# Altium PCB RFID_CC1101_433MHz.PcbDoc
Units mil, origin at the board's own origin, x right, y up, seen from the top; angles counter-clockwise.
Board outline 1500 x 2000 mil, 4 copper layers (Top Layer, GND Plane, POWER Plane, Bottom Layer), stack 16.312 mil thick; 74 components, 57 nets, 265 pads, 134 vias.
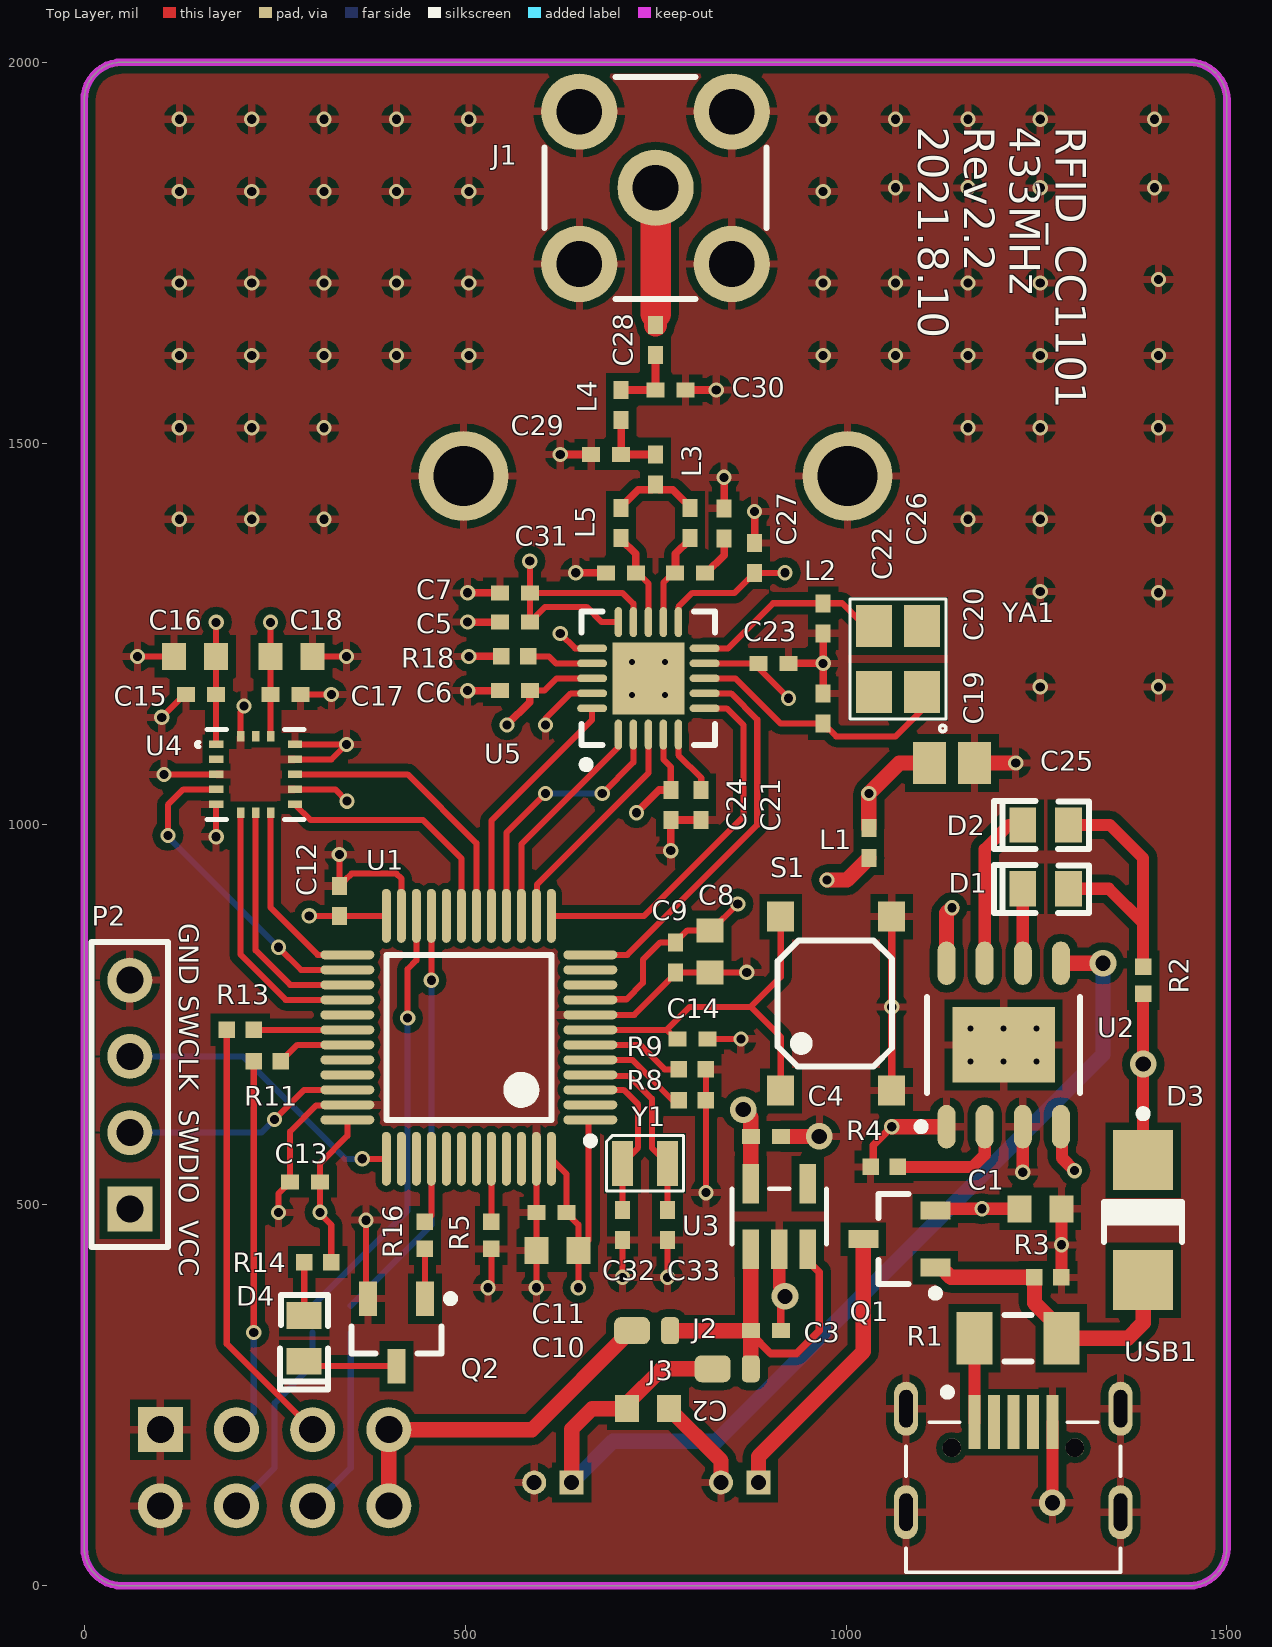
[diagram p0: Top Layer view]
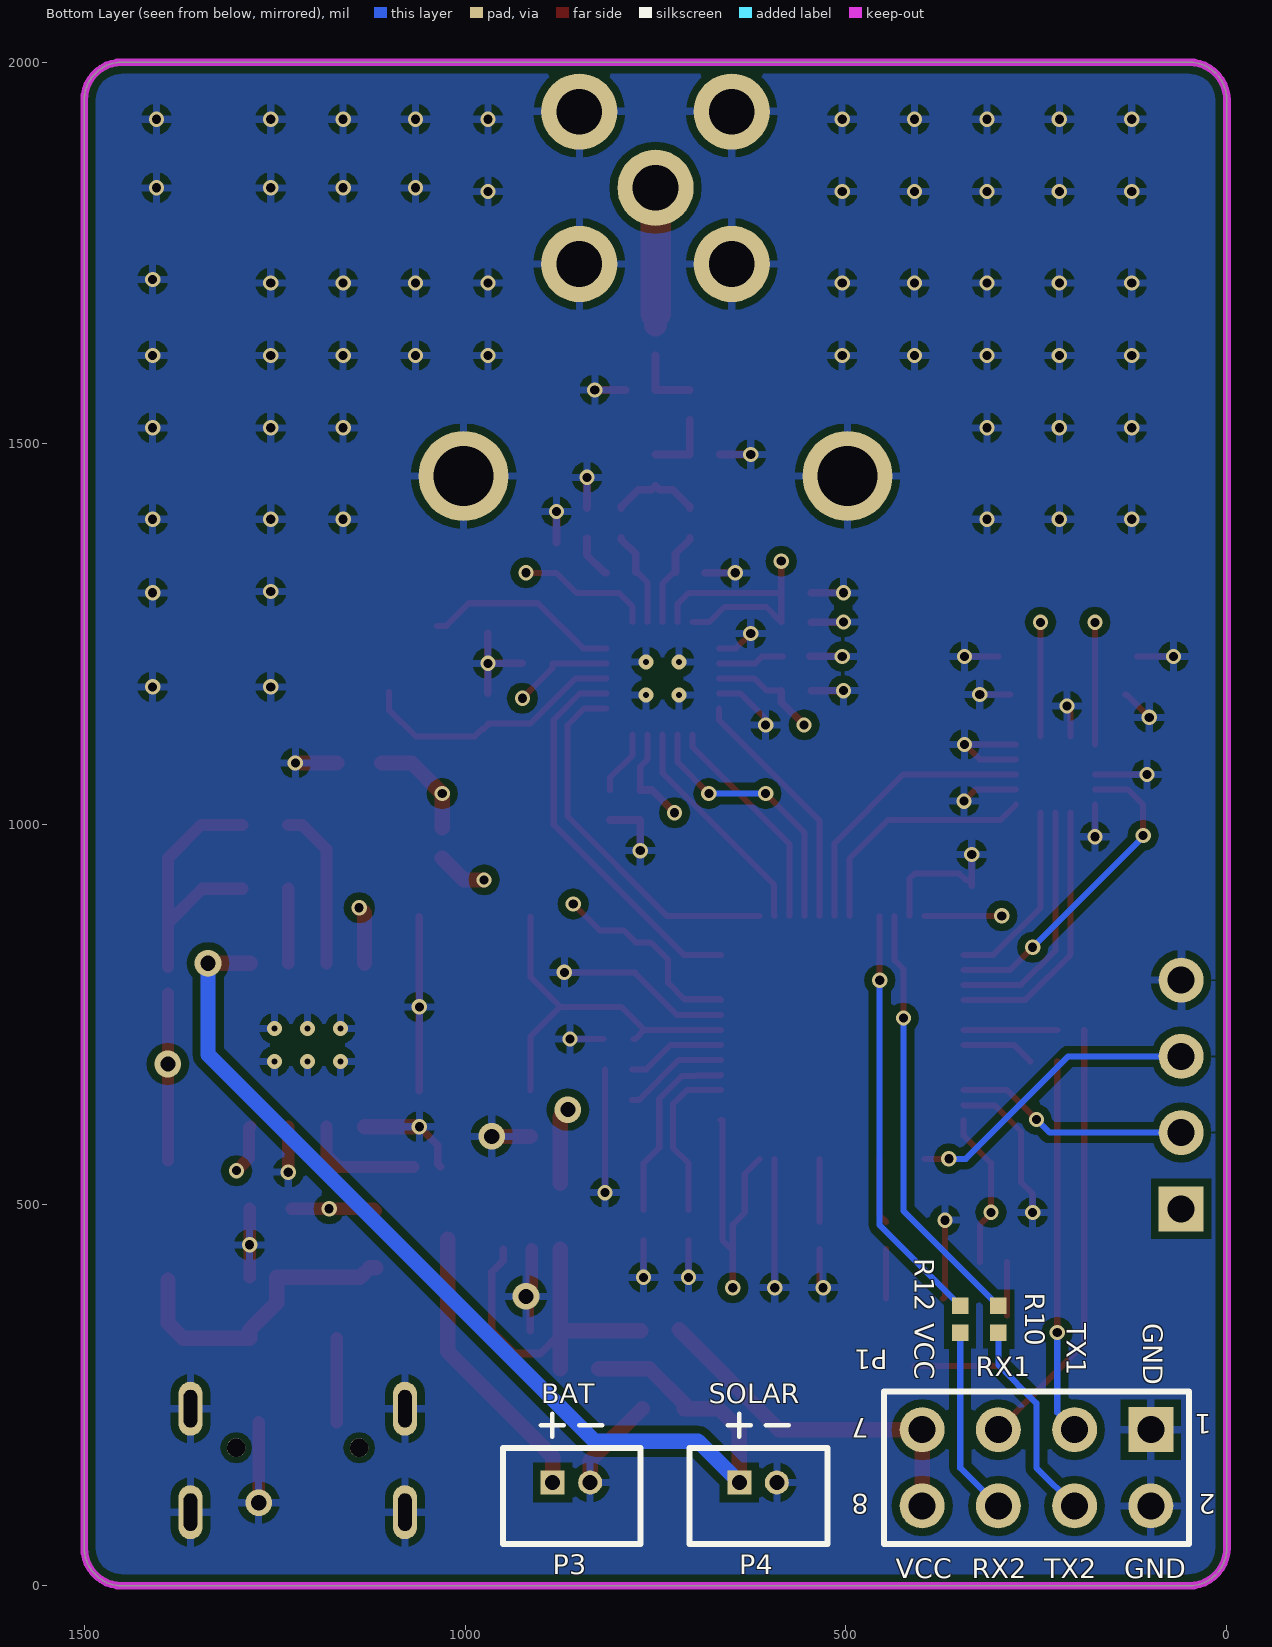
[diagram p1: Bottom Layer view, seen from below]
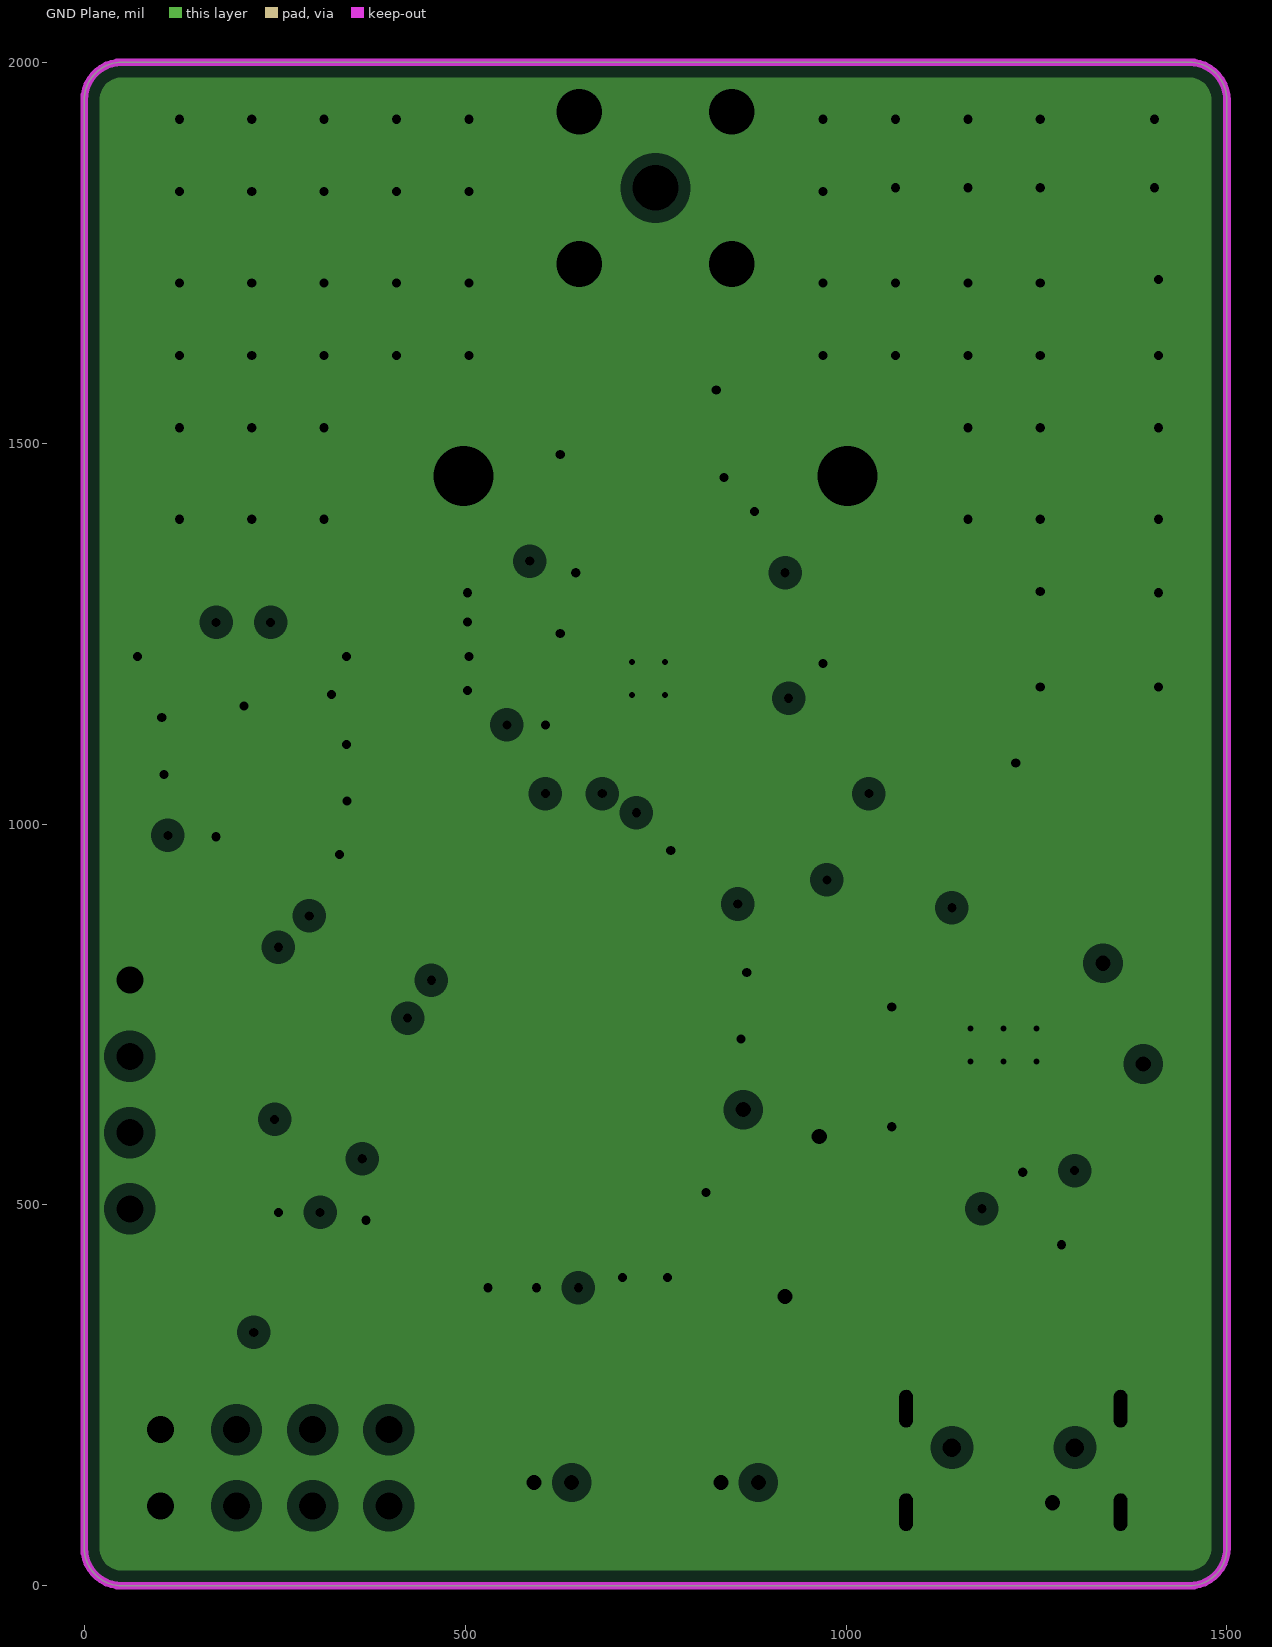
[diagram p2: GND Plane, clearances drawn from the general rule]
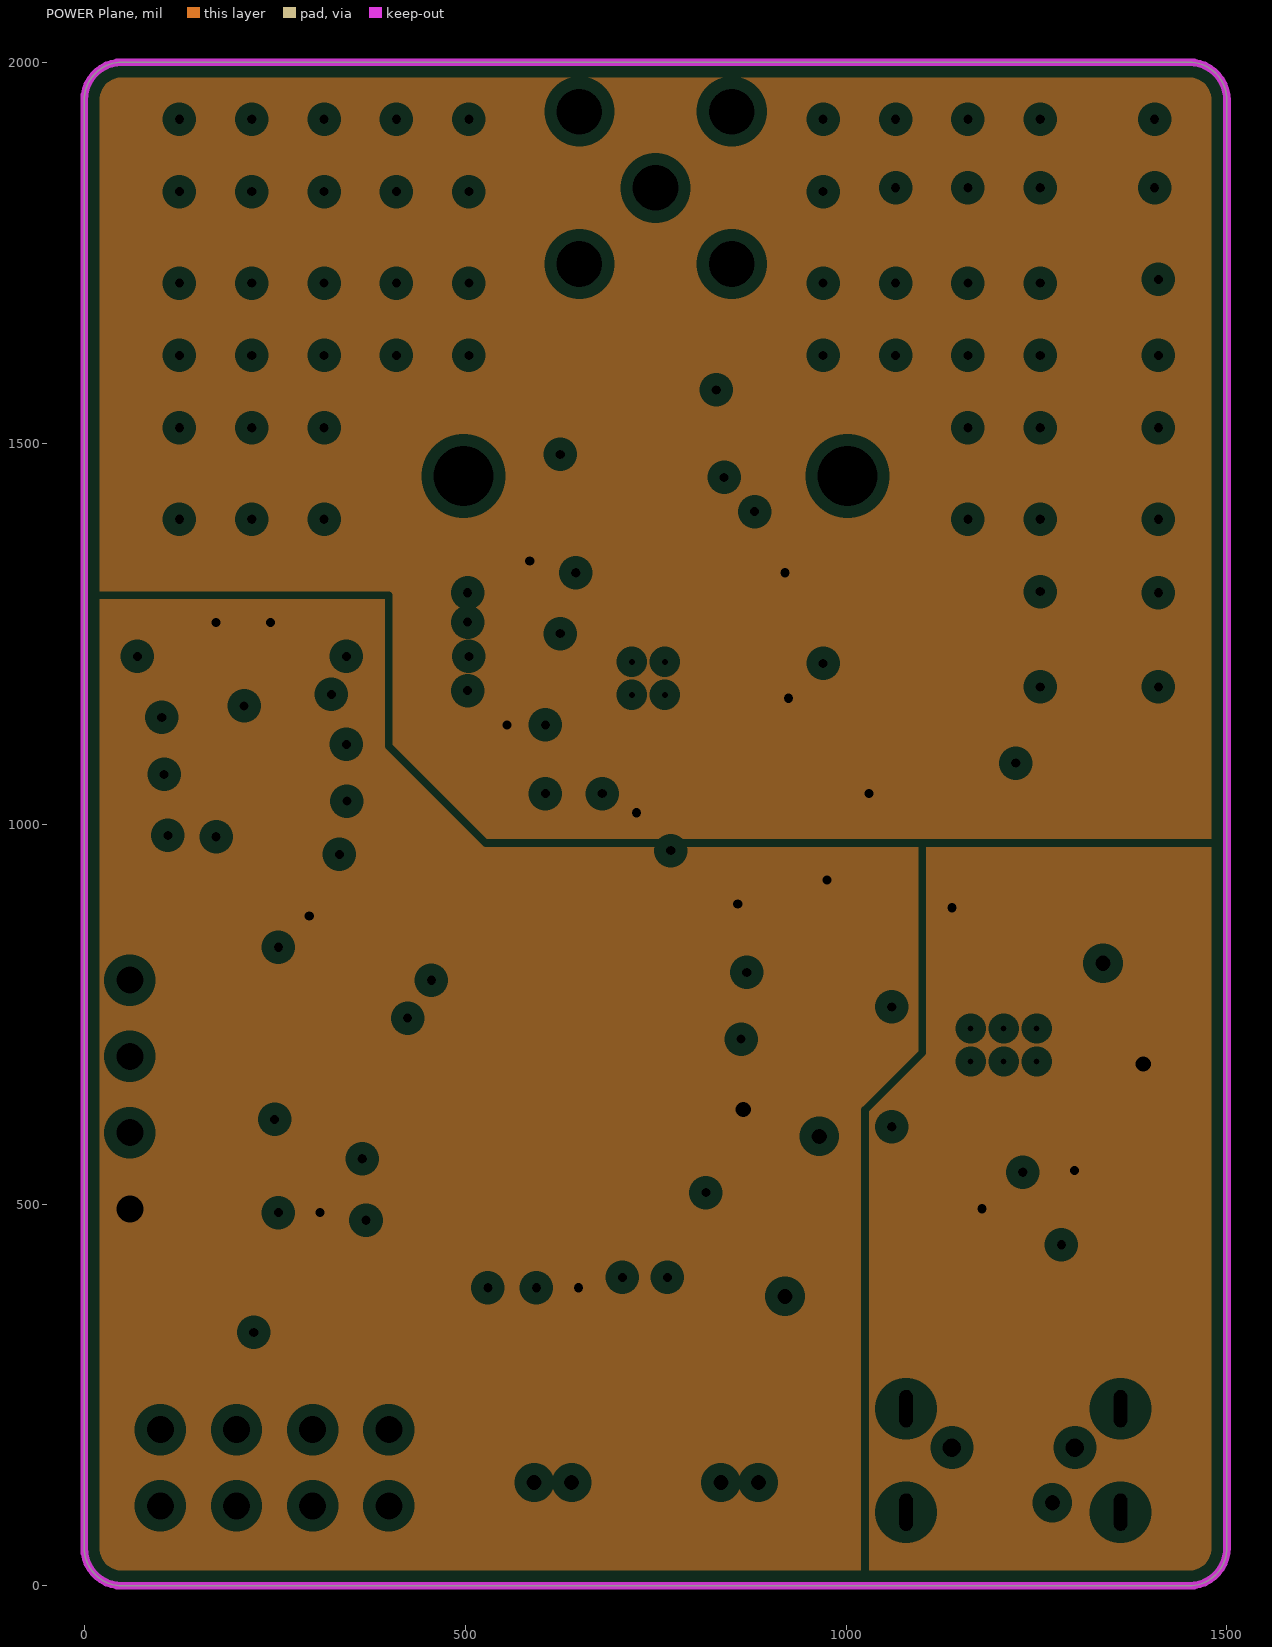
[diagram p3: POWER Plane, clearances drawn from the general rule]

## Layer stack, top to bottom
Top Solder: solder mask 0.4, Solder Resist, Dk 3.5
Top Layer: signal copper 1.3779
Dielectric 1: core 4, Core-009, Dk 4.5
GND Plane: plane copper 1.3779, net GND
Dielectric 3: prepreg 2.8, PP-006, Dk 4.1
POWER Plane: plane copper 1.3779, net (Multiple Nets)
Dielectric 2: core 4, Core-009, Dk 4.5
Bottom Layer: signal copper 1.3779
Bottom Solder: solder mask 0.4, Solder Resist, Dk 3.5

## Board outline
0,50 ccw(c50,50) 50,0 1450,0 ccw(c1450,50) 1500,50 1500,1950 ccw(c1450,1950) 1450,2000 50,2000 ccw(c50,1950) 0,1950

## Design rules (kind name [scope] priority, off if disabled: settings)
Clearance Clearance_8mil [(IsPad and InComponent('U1')) or (IsPad and InComponent('U4')) or (IsPad and InComponent('U5')) or (IsPad and InComponent('USB1'))] p1: gap=8 ignorepadtopadclearanceinfootprint=TRUE
Clearance [All] p2: gap=10 ignorepadtopadclearanceinfootprint=FALSE except(0: Arc-Hole Track-Hole SMDPad-Hole THPad-Hole Via-Hole Fill-Hole Poly-Hole Region-Hole Text-Hole)
MinimumSolderMaskSliver [All] p1: minsoldermaskwidth=1.4
PlaneClearance [All] p1: clearance=16
PlaneConnect [All] p1: pad.planeconnectstyle=Relief pad.reliefexpansion=20 pad.reliefentries=4 pad.reliefconductorwidth=10 pad.reliefairgap=10 via.planeconnectstyle=Relief via.reliefexpansion=16 via.reliefentries=4 via.reliefconductorwidth=10 via.reliefairgap=10
PolygonConnect [All] p1: connectstyle=Relief reliefconductorwidth=10 reliefentries=4 polygonreliefangle="90 Angle" airgapwidth=10
RoutingVias [All] p1: holewidth=12 width=20 viastyle="Through Hole" minholewidth=6 minwidth=16 maxholewidth=28 maxwidth=50
SilkToSilkClearance [All] p1: silktosilkclearance=6
SilkToSolderMaskClearance [IsPad] p1: minsilkscreentomaskgap=0 clearancetoexposedcopper=TRUE
SolderMaskExpansion [All] p1: expansion=4
Width Width_PW [InNet('BAT+') or InNet('SOLAR+') or InNet('VCC') or InNet('VCC_3V') or InNet('VCC_CC1101') or InNet('VCC_5V')] p1: maxlimit=40 minlimit=8 preferedwidth=20
Width [All] p2: maxlimit=40 minlimit=8 preferedwidth=10
25 further rules are at their usual default settings.

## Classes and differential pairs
component class Power: C1 C2 C3 C4 D1 D2 D3 J2 J3 P3 P4 Q1 R1 R2 R3 R4 U2 U3 USB1
component class MEMS&RF: C5 C6 C7 C15 C16 C17 C18 C19 C20 C21 C22 C23 C24 C25 C26 C27 C28 C29 C30 C31 J1 L1 L2 L3 L4 L5 R18 U4 U5 YA1
component class MCU: C8 C9 C10 C11 C12 C13 C14 C32 C33 D4 P1 P2 Q2 R5 R8 R9 R10 R11 R12 R13 R14 R16 S1 U1 Y1

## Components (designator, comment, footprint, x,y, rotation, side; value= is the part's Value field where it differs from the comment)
C1 "10uF" 1608[0603] 1255.12,495 r180 top
C2 "10uF" 1608[0603] 740,232.57 r180 top
C3 "1uF" 0402 894.69,335 r180 top
C4 "1uF" 0402 894.69,590 r180 top
C5 "220pF" 0402 565.32,1265 r180 top
C6 "220pF" 0402 565.31,1175 r0 top
C7 "10nF" 0402 565.31,1303.44 r0 top
C8 "1uF" 1608[0603] 821.4,832.87 r90 top
C9 "100nF" 0402 776.18,825 r90 top
C10 "10uF" 1608[0603] 621.14,440 r0 top
C11 "100nF" 0402 613.27,490 r180 top
C12 "100nF" 0402 335,899.13 r90 top
C13 "100nF" 0402 290,530 r180 top
C14 "100nF" 0402 798.44,717.72 r0 top
C15 "100nF" 0402 153.64,1170 r0 top
C16 "1uF" 1608[0603] 145.77,1220 r180 top
C17 "100nF" 0402 264.38,1170 r0 top
C18 "1uF" 1608[0603] 272.25,1220 r180 top
C19 "12pF" 0402 970,1151.81 r270 top
C20 "15pF" 0402 970,1270 r90 top
C21 "100nF" 0402 810,1025 r90 top
C22 "220pF" 0402 880,1349.37 r90 top
C23 "10nF" 0402 905,1210.87 r180 top
C24 "100nF" 0402 770,1025 r270 top
C25 "1uF" C0805 1138.98,1080 r180 top
C26 "220pF" 0402 840,1394.68 r90 top
C27 "3.9pF" 0402 795,1395 r90 top
C28 "220pF" 0402 750,1635 r90 top
C29 "8.2pF" 0402 685.31,1485 r0 top
C30 "5.6pF" 0402 769.68,1569.69 r180 top
C31 "3.9pF" 0402 705,1329.68 r0 top
C32 "10pF" 0402 706.56,473.86 r90 top
C33 "10pF" 0402 765.62,473.86 r90 top
D1 "Green" 0603/K 1292,915 r180 top
D2 "Red" 0603/K 1292,998.87 r180 top
D3 "SS24S" ONSC-SMA-2-403D-02_V 1390,480 r270 top
D4 "Green" 0603/K 288.91,355 r270 top
J1 "CONSMA002" CON-SMA-RA 750,1835 r0 top
J2 "0Ω" "1608[0603] - JUMPER" 739.21,335 r0 top
J3 "0Ω" "1608[0603] - JUMPER" 845,285 r0 top
L1 "1000Ω@100MHz" 0402 1030,975 r90 top
L2 "27nH" 0402 795,1329.69 r0 top
L3 "22nH" 0402 750,1465.32 r90 top
L4 "27nH" 0402 705,1550 r90 top
L5 "27nH" 0402 705,1395 r90 top
P1 "15446808" HDR2X4-15446808 100,205 r0 bottom
P2 "Header 4" HDR1X4-SWD 60,495 r90 top
P3 "A1251WV-XP-2P" A1251WV-XP-2P 885,135.71 r180 bottom
P4 "A1251WV-XP-2P" A1251WV-XP-2P 640,135.71 r180 bottom
Q1 "Si2301CDS" SOT95P237X112-3N 1070,455 r180 top
Q2 "MMS8050-L" SOT-23B_N 410,332.72 r270 top
R1 "0.4" RESC3216X07N 1225.59,325 r0 top
R2 "1k" RESC1005X04N 1390,795 r90 top
R3 "10k" RESC1005X04N 1264.96,405 r180 top
R4 "1.2k" RESC1005X04N 1050,550 r0 top
R5 "10k" RESC1005X04N 534.53,460 r270 top
R8 "10k" RESC1005X04N 798.44,637.72 r180 top
R9 "10k" RESC1005X04N 798.44,677.87 r180 top
R10 "33" RESC1005X04N 300,350 r270 bottom
R11 "33" RESC1005X04N 240.43,688.35 r180 top
R12 "33" RESC1005X04N 350,350 r270 bottom
R13 "33" RESC1005X04N 205,729.84 r0 top
R14 "10k" RESC1005X04N 306.63,425 r0 top
R16 "1k" RESC1005X04N 447.4,460 r270 top
R18 "56k" RESC1005X04N 565.31,1220 r0 top
S1 "DPST-4" DPST 914.33,650 r90 top
U1 "STM32L051C8T6" STM-LQFP48_N 505,720 r180 top
U2 "TP4056" ESOP-9N 1207,710 r90 top
U3 "ADP151AUJZ-3.0-R7" UJ_5 912.4,485 r90 top
U4 "ADXL362BCCZ" LGA_CC-16-4 225,1065 r0 top
U5 "CC1101" QFN50P400X400X100_HS-21N 740.63,1191.18 r90 top
USB1 "Micro-USB" USB_MICRO_5P4J 1219.69,18 r270 top
Y1 "32.768k" XTAL-2012 706.56,554.68 r0 top
YA1 "26MHz" XTAL-SMT-4P 1100,1173.39 r90 top

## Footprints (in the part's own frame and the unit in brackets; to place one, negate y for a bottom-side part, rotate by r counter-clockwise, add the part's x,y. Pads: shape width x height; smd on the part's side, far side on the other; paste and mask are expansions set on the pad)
0402 [mm] "Chip Capacitor, Body 1.0x0.5mm, IPC High Density"
  rect 0.6x0.5 smd: 1(-0.5,0) 2(0.5,0)
  body extent -0.55,-0.3 0.55,0.3, height 1.3
0603/K [mil]
  rect 35x46 smd: A(0,0) K(60,0)
  silkscreen extent -27,-31 97,31
1608[0603] [mm] "Chip Capacitor, Body 1.6x0.8mm, IPC High Density"
  rect 0.8x0.9 smd: 1(-0.7,0) 2(0.7,0)
  body extent -0.87,-0.48 0.87,0.48, height 1.3
"1608[0603] - JUMPER" [mm] "jumper, Body 1.6x0.8mm, IPC High Density"
  rrect50% 1.2x0.9 smd: 1(-0.508,0)
  rrect50% 0.6x0.9 smd: 2(0.762,0)
  body extent -0.87,-0.48 0.87,0.48, height 1.3
A1251WV-XP-2P [mm] "Connector; Header; 2 Position"
  rect 0.8x0.8 hole 0.5: 1(0,0)
  round 0.8 hole 0.5: 2(1.25,0)
  silkscreen extent -1.66,-2.05 2.93,2.29
C0805 [mm] "Chip Capacitor, Body 2.0x1.3mm, IPC High Density"
  rect 1.1x1.4 smd: 1(-0.75,0) 2(0.75,0)
  body extent -1.1,-0.72 1.1,0.72, height 1.4
CON-SMA-RA [mil] "Connector, SMA Female, 5-Lead, Thru-Hole, Right-Angle, Body 7x7mm"
  round 100 hole 60: 1(0,0) 2(-100,100) 3(100,100) 4(100,-100) 5(-100,-100)
  silkscreen extent -146,-146 146,146
DPST [mm]
  rect 1x0.9 smd: 1(0,0) 2(5.8,0) 3(0,-3.7) 4(5.8,-3.7)
  silkscreen extent 0.81,-3.71 5,0.1
ESOP-9N [mm] "ESOP, 8-Leads, Body 4.90x3.90mm, Pitch 1.27mm, Thermal Pad 3.41x2.52mm, IPC Medium Density, For TP4056"
  oval 1.45x0.6 smd: 1(-2.725,1.905) 2(-2.725,0.635) 3(-2.725,-0.635) 4(-2.725,-1.905) 5(2.725,-1.905) 6(2.725,-0.635) 7(2.725,0.635) 8(2.725,1.905)
  rect 2.52x3.41 smd: 9(0,0)
  silkscreen extent -2.85,-2.55 1.6,2.88, body extent -3,-2.55 3,2.55, height 1.75
HDR1X4-SWD [mm] "Connector; Header; 4 Position"
  rect 1.5x1.5 hole 0.9: 1(0,0)
  round 1.5 hole 0.9: 2(2.54,0) 3(5.08,0) 4(7.62,0)
  silkscreen extent -1.27,-1.27 8.89,1.27
HDR2X4-15446808 [mm] "Connector; Header; 4x2 Position"
  rect 1.5x1.5 hole 0.9: 1(0,0)
  round 1.5 hole 0.9: 2(0,2.54) 3(2.54,0) 4(2.54,2.54) 5(5.08,0) 6(5.08,2.54) 7(7.62,0) 8(7.62,2.54)
  silkscreen extent -1.27,-1.27 8.89,3.81
LGA_CC-16-4 [mm]
  rect 0.475x0.25 smd: 1(-1.313,1) 2(-1.313,0.5) 3(-1.313,0) 4(-1.313,-0.5) 5(-1.313,-1) 9(1.313,-1) 10(1.313,-0.5) 11(1.313,0) 12(1.313,0.5) 13(1.313,1)
  rect 0.25x0.35 smd: 6(-0.5,-1.275) 7(0,-1.275) 8(0.5,-1.275) 14(0.5,1.275) 15(0,1.275) 16(-0.5,1.275)
  silkscreen extent -1.98,-1.5 1.63,1.5, body extent 0,0 0.25,0.25, height 0.25
ONSC-SMA-2-403D-02_V [mm] "Molded, 2-Leads, Body 4.57x2.92mm"
  rect 2x2 smd: 1(-2,0) 2(2,0)
  silkscreen extent -3.67,-1.3 0.74,1.3, body extent -2.16,-1.3 2.16,1.3, height 2.2
QFN50P400X400X100_HS-21N [mm] "QFN, 20-Leads, Body 4.00x4.00mm, Pitch 0.50mm, Thermal Pad 2.40x2.40mm, IPC Medium Density"
  oval 1x0.25 smd: 1(-1.875,1) 2(-1.875,0.5) 3(-1.875,0) 4(-1.875,-0.5) 5(-1.875,-1) 11(1.875,-1) 12(1.875,-0.5) 13(1.875,0) 14(1.875,0.5) 15(1.875,1)
  oval 0.25x1 smd: 6(-1,-1.875) 7(-0.5,-1.875) 8(0,-1.875) 9(0.5,-1.875) 10(1,-1.875) 16(1,1.875) 17(0.5,1.875) 18(0,1.875) 19(-0.5,1.875) 20(-1,1.875)
  rect 2.4x2.4 smd: 21(0,0)
  silkscreen extent -3,-2.22 2.22,2.22, body extent -2.08,-2.08 2.08,2.08, height 1
RESC1005X04N [mm] "Chip Resistor, 2-Leads, Body 1.00x0.50mm, IPC Medium Density"
  rect 0.55x0.55 smd: 1(-0.45,0) 2(0.45,0)
  body extent -0.53,-0.28 0.53,0.28, height 0.4
RESC3216X07N [mm] "Chip Resistor, 2-Leads, Body 3.20x1.60mm, IPC Medium Density"
  rect 1.2x1.75 smd: 1(-1.45,0) 2(1.45,0)
  silkscreen extent -0.45,-0.77 0.45,0.77, body extent -1.7,-0.87 1.7,0.87, height 0.65
SOT95P237X112-3N [mm] "SOT23, 3-Leads, Body 2.92x2.37mm, Pitch 0.95mm, IPC Medium Density"
  rect 1x0.6 smd: 1(-1.2,0.95) 2(-1.2,-0.95) 3(1.2,0)
  silkscreen extent -1.33,-1.5 0.7,1.92, body extent -1.32,-1.52 1.32,1.52, height 1.12
SOT-23B_N [mm] "SOT23, 3-Leads, Body 2.9x1.3mm, Pitch 0.95mm, Lead Span 2.4mm, IPC Medium Density"
  rect 1.15x0.6 smd: B(-1.125,0.95) C(1.125,0) E(-1.125,-0.95)
  silkscreen extent -1.25,-1.5 0.7,1.93, body extent -0.7,-1.5 0.7,1.5, height 1.14
STM-LQFP48_N [mm] "QFP, 48-Leads, Body 7x7mm, Pitch 0.5mm, IPC Medium Density"
  oval 1.8x0.3 smd: 1(-4.05,2.75) 2(-4.05,2.25) 3(-4.05,1.75) 4(-4.05,1.25) 5(-4.05,0.75) 6(-4.05,0.25) 7(-4.05,-0.25) 8(-4.05,-0.75) 9(-4.05,-1.25) 10(-4.05,-1.75) 11(-4.05,-2.25) 12(-4.05,-2.75) 25(4.05,-2.75) 26(4.05,-2.25) 27(4.05,-1.75) 28(4.05,-1.25) 29(4.05,-0.75) 30(4.05,-0.25) 31(4.05,0.25) 32(4.05,0.75) 33(4.05,1.25) 34(4.05,1.75) 35(4.05,2.25) 36(4.05,2.75)
  oval 0.3x1.8 smd: 13(-2.75,-4.05) 14(-2.25,-4.05) 15(-1.75,-4.05) 16(-1.25,-4.05) 17(-0.75,-4.05) 18(-0.25,-4.05) 19(0.25,-4.05) 20(0.75,-4.05) 21(1.25,-4.05) 22(1.75,-4.05) 23(2.25,-4.05) 24(2.75,-4.05) 37(2.75,4.05) 38(2.25,4.05) 39(1.75,4.05) 40(1.25,4.05) 41(0.75,4.05) 42(0.25,4.05) 43(-0.25,4.05) 44(-0.75,4.05) 45(-1.25,4.05) 46(-1.75,4.05) 47(-2.25,4.05) 48(-2.75,4.05)
  silkscreen extent -4.18,-2.75 2.75,3.57, body extent -3.5,-3.5 3.5,3.5, height 1.6
UJ_5 [mil] "5P,TSOT for ADP151AUJZ"
  rect 52x22 smd paste+0 mask+0: 1(-43,37.4) 2(-43,0) 3(-43,-37.4) 4(43,-37.4) 5(43,37.4)
  silkscreen extent -37,-62 37,62, body extent -55,-57 55,57, height 39
USB_MICRO_5P4J [mm] "MK5P, Base, DIP, With locating column, roll edge."
  oval 1.8x0.8 hole 0.45 slot 1.25 at 0 deg: 0(-5.45,3.575) 0(-5.45,-3.575) 0(-2,3.575) 0(-2,-3.575)
  rect 1.8x0.4 smd: 1(-5,-1.3) 2(-5,-0.65) 3(-5,0) 4(-5,0.65) 5(-5,1.3)
  round 0.62 hole 0.62 unplated: MH1(-4.15,2.05) MH2(-4.15,-2.05)
  silkscreen extent -6.12,-3.57 0,3.57
XTAL-2012 [mm] "NX2012SA, 2 pins, 2.0mmx1.2mm."
  rect 0.7x1.5 smd: 1(0,0) 2(1.5,0)
  silkscreen extent -0.53,-0.92 2.03,0.92
XTAL-SMT-4P [mm] "3225, 3.2mmx2.5mm"
  rect 1.4x1.2 smd: 1(0,0) 2(2.2,0) 3(2.2,1.6) 4(0,1.6)
  silkscreen extent -1.32,-0.8 3.1,2.4

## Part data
C1 C2 C10: library part C1608X5R1A106K080AC, "Capacitor (0603,X5R,10uF,DC 10V,±10%) TDK"
C3 C4: library part C1005X5R1E105K050BC, "Capacitor (0402,X5R,1uF,DC 25V,±10%) TDK"
C5 C6 C22 C26 C28: library part GRM1555C1H221JA01D, "Capacitor (0402,NP0,220pF,DC 50V,±5%) Murata"
C7 C23: library part GRM155R71E103KA01D, "Capacitor (0402,X7R,10nF,DC 25V,±10%) Murata"
C8 C16 C18: library part CGA3E2X5R1A105K080AA, "Capacitor (0603,X5R,1uF,DC 10V,+/-10%) TDK"
C9 C11 C12 C13 C14: library part CGA2B2X5R1A104K050BA, "Capacitor (0402,X5R,100nF,DC 10V,±10%) TDK"
C15 C17: library part C1005X7R1H104K050BE, "Capacitor (0402,X7R,100nF,DC 50V,±10%) TDK"
C19: library part GRM1555C1H120JZ01D, "Capacitor (0402,NP0,12pF,DC 50V,±5%) Murata"
C20: library part GRM1555C1H150JZ01D, "Capacitor (0402,NP0,15pF,DC 50V,±5%) Murata"
C21 C24: library part GRM155R71A104KA01D, "Capacitor (0402,X5R,100nF,DC 10V,±10%) Murata"
C25: library part GRM21BR71C105KA01L, "Capacitor (0805,X7R,1uF,DC 16V,±10%) Murata"
C27 C31: library part GRM1555C1H3R9CZ01D, "Capacitor (0402,NP0,3.9pF,DC 50V,±0.25pF) Murata"
C29: library part GRM1555C1H8R2CZ01D, "Capacitor (0402,NP0,8.2pF,DC 50V,±0.25pF) Murata"
C30: library part GRM1555C1H5R6CZ01D, "Capacitor (0402,NP0,5.6pF,DC 50V,±0.25pF) Murata"
C32 C33: library part CC0402DRNPO8BN100, "Capacitor (0402,NPO,10pF,DC 25V,±0.5pF) YAGEO"
D1 D4: library part TLMG1100-GS08, "Standard 0603 SMD LED, Green, 2.1V,-40 °C to +100 °C"
D2: library part TLMS1100-GS08, "Standard 0603 SMD LED, Red, 2.1V,-40 °C to +100 °C"
D3: "Schottky Power Rectifier, 2-Pin SMA, VRRM=40V , VF=0.517V at IF=2.0A , Pb-Free, Tape and Reel", Manufacturer="On Semiconductor", Supplier Part Number 1=SS16T3GOSTR-ND
J1: "SMA Female Right Angle PCB Mount Connector"
J2 J3: library part JUMP-0603, "jumper 0603(1608)"
L1: library part BLM15HG102SN1D, "Inductor,EMI filter bead, 1000Ω@100MHz 250mA, 0402 1k ohms Tape GHz Band Gen Use, Murata"
L2 L4 L5: library part LQG15HS27NJ02D, "Inductor, 27n, 0402, ±5% / Murata"
L3: library part LQG15HS22NJ02D, "Inductor, 22n, 0402, ±5% / Murata"
P1: "Header, 4-Pin, Dual row, 2.54mm Pitch C-Grid Receptacle, Through Hole, Dual Row, High Profile, Vertical, High-Temperature, 8 Circuits", Manufacturer=molex
P2: "Header, 4-Pin"
P3 P4: "Header, 2-Pin"
Q1: "P-Channel MOSFET,VDS=-20V,VGS=8V,ID=3.1A,VGS(th)Min=0.4V,SOT-23"
Q2: "NPN Silicon  Plastic-Encapsulate  Transistor , MCC , Range:120-200"
R1: library part PE1206FRF470R4L, "Resistor 1206(3216) 0.4Ω ±1% 1W AUTOMOTIVE GRADEPE_L series"
R2 R16: library part RC0402FR-071KL, "Resistor 0402(1005) 1kΩ ±1%"
R3 R5 R8 R9 R14: library part RC0402FR-0710KL, "Resistor 0402(1005) 10kΩ ±1%"
R4: library part RC0402FR-071K2L, "Resistor 0402(1005) 1.2kΩ ±1%"
R10 R11 R12 R13: library part RC0402FR-0733RL, "Resistor 0402(1005) 33Ω ±1%"
R18: library part RK73H1ETTP5602F, "Resistor, 56k ohms, 0402, ±1% Koa"
S1: library part CX-G001, "5.2*5.2轻触开关"
U1: "Access line ultra-low-power 32-bit MCU Arm?-based Cortex?-M0+, 64 KB Flash, 8 KB SRAM,2 KB EEPROM, 38 fast I/Os, 48-pin LQFP, -40 to 125 degC, Tray", I/Os (High Current)=37, Operating Frequency(F) (Processor speed) (MHz)=32, Supplier Part Number 1=497-11517-ND, Supply Voltage(Vcc) min (V)=2
U2: "1A线性锂离子电池充电器"
U3: library part ADP151, "The ADP151 is an ultralow noise, low dropout (LDO) linear regulator that operates from 2.2 V to 5.5 V and provides up to 200 mA of output current.", Dropout Voltage(mV)=140
U4: "ADXL362, LGA, CC-16-4."
U5: "Low-Power Sub-1GHz RF Transceiver"
USB1: library part USB/Micro-AB, "Receptacle,Micro 5脚贴片 不带定位柱"
Y1: library part NX2012SA-32.768K, "Crystal Oscillator, SMT-2012, 2 Pins, NX2012SA-32.768K."
YA1: library part NX3225GA-26M, "Crystal, 26.000000MHz, 10.0pF, 50 ohms max, 20/40 ppm, -40C to +85C / , NDK"

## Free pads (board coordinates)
  round 118.11 hole 78.74: 6(498.03,1456.69) 7(1001.97,1456.69)

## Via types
v1: diameter 20, hole 12, Top Layer to Bottom Layer, 118 vias
v2: diameter 19.68, hole 7.87, Top Layer to Bottom Layer, 10 vias
v3: diameter 35, hole 20, Top Layer to Bottom Layer, 6 vias

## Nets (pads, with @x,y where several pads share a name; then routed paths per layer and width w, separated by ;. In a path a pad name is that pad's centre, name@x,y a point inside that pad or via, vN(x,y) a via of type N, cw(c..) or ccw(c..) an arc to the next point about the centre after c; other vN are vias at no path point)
BAT+: C2.2 J3.1 P4.1 U2.5 | length 1396.9
  Top Layer w20: P4.1 640,205.76 666.81,232.57 C2.2 712.44,239.2 758.24,285 J3.1 ; U2.5 v3(1337.28,817.28)
  Bottom Layer w20: P4.1 694.29,190 830,190 1337.28,697.28 v3(1337.28,817.28)
GDO0: U1.13 U5.6 | length 486.3
  Top Layer w8: U1.13 735,879.45 865.55,1010 865.55,1129.6 843.34,1151.81 U5.6
GDO2: U1.14 U5.3 | length 298.8
  Top Layer w8: U1.14 594.31,880.18 594.31,920.37 740.63,1066.69 U5.3
GND: C1.1 C2.1 C3.1 C4.1 C5.2 C6.1 C7.1 C8.1 C9.1 C10.1 C11.2 C12.2 C13.2 C14.2 C15.1 C16.2 C17.2 C18.1 C19.1 C20.1 C21.1 C22.2 C23.1 C24.2 C25.1 C26.2 C29.1 C30.1 C31.1 C32.1 C33.1 J1.2 J1.3 J1.4 J1.5 P1.1 P1.2 P2.4 P3.2 P4.2 pad.6 pad.7 Q2.E R3.1 R4.1 R5.2 R8.1 R9.1 R18.1 S1.3 S1.4 U1.8 U1.23 U1.35 U1.47 U2.1 U2.3 U2.9 U3.2 U4.3 U4.5 U4.10 U4.12 U4.13 U4.16 U5.16 U5.19 U5.21 USB1.0 USB1.5 | length 3462.4
  Top Layer w8: v1(70,1220) C16.2 ; v1(101.99,1140) 131.99,1170 C15.1 ; v1(105,1065) U4.3 ; v1(173.33,983.33) U4.5 ; U4.16 205.31,1147.06 210,1151.75 v1(210,1155) ; v1(255,490) 255,514.68 C13.2 270.31,596.4 304.6,630.69 344.82,630.69 U1.35 ; U4.10 329.69,1045.31 v1(345,1030) ; U4.12 324.69,1084.69 v1(344.38,1104.38) U4.13 ; C17.2 v1(324.53,1170) ; C18.1 v1(344.38,1220) ; C12.2 C12.2@335,920.79 ; v1(335,960) C12.2@335,920.79 ; v1(370,480) 370,379.61 Q2.E ; U1.23 416.42,928.58 410,935 351.18,935 342.81,926.63 340.84,926.63 C12.2@335,920.79 ; v1(530,391.42) 534.53,395.94 R5.2 ; v1(593.58,391.42) C10.1 C11.2 U1.47 ; v1(605.46,1130) 605.46,1138.13 638.82,1171.5 U5.19 ; v1(625,1250) 644.45,1230.55 U5.16 ; U1.8 722.36,749.53 776.18,803.35 C9.1 C8.1 v1(869.68,805.32) ; v1(706.56,405) C32.1 ; v1(765.62,405) C33.1 ; v1(816.15,516.15) R8.1 R9.1 ; C14.2 v1(862.28,717.72)
  Top Layer w10: v1(503.44,1175) C6.1 ; v1(503.44,1265) C5.2 ; v1(503.44,1303.44) C7.1 ; v1(505,1220) R18.1 ; v1(625,1485) C29.1 ; v1(645.31,1329.69) C31.1 ; v1(770,965) C24.2 C21.1 ; C30.1 v1(829.68,1569.68) ; C26.2 v1(840,1455) ; C22.2 v1(880,1410) ; C3.1 914.37,374.37 v3(920,380) ; C23.1 v1(970,1210.87) ; C19.1 v1(970,1210.87) ; C20.1 v1(970,1210.87) ; R4.1 1035.82,553.53 1035.82,578.53 v1(1060,602.72) ; S1.3 v1(1060,760) S1.4
  Top Layer w16: U3.2 912.4,392.74 920,385.14 v3(920,380) ; v1(1232,543) U2.3 ; v3(1270.87,109.13) USB1.5 ; R3.1 v1(1282.68,447.68) C1.1
  Top Layer w20: C2.1 835.79,164.34 P3.2 ; C4.1 v3(965,590) ; v1(1060,602.72) U2.1 ; C25.1 v1(1222.72,1080)
  other v1: 1255,1180 1410,1180 1410,1303.44 1255,1305 125,1400 220,1400 315,1400 1160,1400 1255,1400 1410,1400 125,1520 220,1520 315,1520 1160,1520 1255,1520 1410,1520 125,1615 220,1615 315,1615 410,1615 505,1615 970,1615 1065,1615 1160,1615 1255,1615 1410,1615 125,1710 220,1710 315,1710 410,1710 505,1710 970,1710 1065,1710 1160,1710 1255,1710 1410,1714.68 125,1830 220,1830 315,1830 410,1830 505,1830 970,1830 1065,1835 1160,1835 1255,1835 1405,1835 125,1925 220,1925 315,1925 410,1925 505,1925 970,1925 1065,1925 1160,1925 1255,1925 1405,1925
  other v2: 1163.69,688.35 1207,688.35 1250.31,688.35 1163.69,731.65 1207,731.65 1250.31,731.65 718.98,1169.53 762.28,1169.53 718.98,1212.83 762.28,1212.83
INT1: U1.18 U4.11 | length 370.9
  Top Layer w8: U4.11 424.68,1065 514.84,974.84 U1.18
INT2: U1.19 U4.9 | length 323.2
  Top Layer w8: U4.9 297.3,1005 445,1005 495.16,954.84 U1.19
LED_GREEN: R16.1 U1.40 | length 86.3
  Top Layer w8: R16.1 455.79,486.1 U1.40
LPUART1_RX: R10.1 U1.22 | length 568.1
  Top Layer w8: v1(424.68,745.32) 424.68,809.68 436.1,821.1 U1.22
  Bottom Layer w8: R10.1 424.68,492.4 v1(424.68,745.32)
LPUART1_TX: R12.1 U1.21 | length 555.6
  Top Layer w8: v1(455.79,795) U1.21
  Bottom Layer w8: R12.1 455.79,473.5 v1(455.79,795)
NetC3_2: C3.2 J2.2 J3.2 U3.1 U3.3 | length 489.5
  Top Layer w10: C3.2 875,331.5 901.5,305 935,305 965,335 965,411.8 949.8,427 U3.3
  Top Layer w20: J2.2 C3.2 U3.1 ; J3.2 C3.2@875,331.5
NetC14_1: C14.1 S1.1 S1.2 U1.7 | length 503.1
  Top Layer w8: U1.7 764.66,729.84 ; C14.1 776.78,717.72 764.66,729.84 ; S1.1 914.33,720.67 875,760 ; S1.2 914.33,799.33 875,760 ; 764.66,729.84 794.82,760 875,760
NetC19_2: C19.2 U5.8 YA1.1 | length 356.1
  Top Layer w8: U5.8 854.88,1191.18 913.94,1132.13 C19.2 970,1130.16 975.84,1124.31 977.81,1124.31 987.13,1115 1065,1115 1100,1150 YA1.1
NetC20_2: C20.2 U5.10 YA1.3 | length 259.3
  Top Layer w8: U5.10 845.15,1230.55 904.29,1289.69 C20.2 995,1289.69 1024.69,1260 YA1.3
NetC21_2: C21.2 U5.5 | length 85.1
  Top Layer w8: U5.5 780,1090.46 810,1060.46 C21.2
NetC26_1: C26.1 L2.2 | length 57
  Top Layer w10: L2.2 816.65,1329.69 840,1353.03 C26.1
NetC27_1: C27.1 L2.1 U5.12 | length 125.8
  Top Layer w8: U5.12 760.31,1316.65 774.21,1330.55 L2.1@776.18,1330.55
  Top Layer w10: L2.1@776.18,1330.55 776.18,1354.53 795,1373.35 C27.1
NetC27_2: C27.2 L3.1 L5.2 | length 116.3
  Top Layer w10: L5.2 705,1416.65 727.17,1438.82 745.16,1438.82 750,1443.66 754.84,1438.82 772.83,1438.82 795,1416.65 C27.2
NetC28_1: C28.1 C30.2 L4.2 | length 90.6
  Top Layer w10: L4.2 C30.2 C28.1
NetC28_2: C28.2 J1.1 | length 180.3
  Top Layer w30: C28.2 750,1670
  Top Layer w40: 750,1670 J1.1
NetC29_2: C29.2 L3.2 L4.1 | length 90.3
  Top Layer w10: L4.1 C29.2 L3.2
NetC31_2: C31.2 L5.1 U5.13 | length 126.2
  Top Layer w8: C31.2@723.82,1330.55 725.79,1330.55 740.63,1315.71 U5.13
  Top Layer w10: L5.1 705,1373.35 723.82,1354.53 C31.2@723.82,1330.55
NetC32_2: C32.2 U1.3 Y1.1 | length 217.5
  Top Layer w8: U1.3@664.45,651.01 708.08,651.01 727.17,631.92 727.17,575.29 Y1.1 C32.2
NetC33_2: C33.2 U1.4 Y1.2 | length 248
  Top Layer w8: U1.4 665.18,670.06 697.4,670.06 698.45,669.01 715.54,669.01 745.17,639.38 745.17,575.14 Y1.2 C33.2
NetD1_A: D1.A D2.A R2.2 | length 375.1
  Top Layer w16: D1.A 1345,915 1390,870 ; D2.A 1346.13,998.87 1390,955 1390,870 ; R2.2 1390,870
NetD1_K: D1.K U2.6 | length 97.7
  Top Layer w16: U2.6 D1.K
NetD2_K: D2.K U2.7 | length 212.9
  Top Layer w16: U2.7 1182,967 1213.87,998.87 D2.K
NetD3_2: D3.2 Q1.1 R1.2 R3.2 | length 401.8
  Top Layer w20: Q1.1 1125.12,417.6 1137.72,405 R3.2 1247.24,371.26 1282.68,335.83 R1.2 1370,325 1390,345 D3.2
NetD4_A: D4.A R14.1 | length 70
  Top Layer w8: D4.A R14.1
NetD4_K: D4.K Q2.C | length 123.8
  Top Layer w8: D4.K 295.49,288.43 Q2.C
NetP1_3: P1.3 R11.2 | length 492.8
  Top Layer w8: v1(222.72,332.72) R11.2
  Bottom Layer w8: P1.3 222.72,227.72 v1(222.72,332.72)
NetP1_4: P1.4 R10.2 | length 268.7
  Bottom Layer w8: P1.4 250,155 250,240 300,290 R10.2
NetP1_5: P1.5 R13.1 | length 571.5
  Top Layer w8: R13.1 187.28,317.72 P1.5
NetP1_6: P1.6 R12.2 | length 248
  Bottom Layer w8: P1.6 350,155 R12.2
NetQ2_B: Q2.B R16.2 | length 65.3
  Top Layer w8: Q2.B R16.2
NetR1_1: R1.1 USB1.1 | length 110.1
  Top Layer w16: USB1.1 R1.1
NetR4_2: R4.2 U2.2 | length 157.8
  Top Layer w16: R4.2 1166.26,550 1182,565.74 U2.2
NetR5_1: R5.1 U1.44 | length 82.8
  Top Layer w8: R5.1 U1.44
NetR8_2: R8.2 U1.5 | length 138.1
  Top Layer w8: U1.5 719.53,690.47 772.28,637.72 R8.2
NetR9_2: R9.2 U1.6 | length 129.6
  Top Layer w8: U1.6 729.84,710.16 762.13,677.87 R9.2
NetR18_2: R18.2 U5.17 | length 87.6
  Top Layer w8: R18.2 610,1220 619.13,1210.87 U5.17
SOLAR+: P3.1 Q1.3 | length 376.4
  Top Layer w20: P3.1 885,170 1022.76,307.76 Q1.3
SPI1_CS: U1.12 U5.7 | length 511.3
  Top Layer w8: U1.12 712.95,828.27 883.55,998.87 883.55,1137.06 849.11,1171.5 U5.7
SPI1_MISO: U1.16 U5.2 | length 350.6
  Top Layer w8: U1.16 554.21,988.76 v1(605.46,1040) ; v1(680,1040) 720.94,1080.94 U5.2
  Bottom Layer w8: v1(605.46,1040) v1(680,1040)
SPI1_MOSI: U1.17 U5.20 | length 327.2
  Top Layer w8: U1.17 534.53,1004.53 666.81,1136.81 U5.20
SPI1_SCLK: U1.15 U5.1 | length 290.7
  Top Layer w8: U1.15 573.9,973.44 701.26,1100.8 U5.1
SPI2_CS: U1.25 U4.8 | length 251.1
  Top Layer w8: U4.8 244.69,890.31 306.73,828.27 U1.25
SPI2_MISO: U1.27 U4.7 | length 319.8
  Top Layer w8: U4.7 225,834.33 270.43,788.9 U1.27
SPI2_MOSI: U1.28 U4.6 | length 351.1
  Top Layer w8: U4.6 205.31,828.56 264.66,769.21 U1.28
SPI2_SCLK: U1.26 U4.4 | length 421.4
  Top Layer w8: v1(110,985) 110,1025 130.31,1045.31 U4.4 ; v1(255,838.27) 284.68,808.58 U1.26
  Bottom Layer w8: v1(110,985) 110,983.27 v1(255,838.27)
SWCLK: P2.3 U1.37 | length 392.4
  Top Layer w8: v1(365,560.55) U1.37
  Bottom Layer w8: P2.3 208.36,695 342.81,560.55 v1(365,560.55)
SWDIO: P2.2 U1.34 | length 308.8
  Top Layer w8: v1(250,612.19) 288.91,651.1 U1.34
  Bottom Layer w8: P2.2 232.81,595 v1(250,612.19)
USART1_RX: R11.1 U1.31 | length 96.4
  Top Layer w8: R11.1 279.96,710.16 U1.31
USART1_TX: R13.2 U1.30 | length 122.8
  Top Layer w8: R13.2 U1.30
VCC: C1.2 D3.1 Q1.2 R2.1 U2.4 U2.8 | length 470.7
  Top Layer w16: Q1.2 1119.84,495 v1(1178.36,495) C1.2 ; U2.4 1283.46,601.26 1283.46,561.54 v1(1300,545) ; D3.1 v3(1390,685) R2.1
  Top Layer w20: U2.8 1132,883.02 v1(1138.98,890)
VCC_3V: C4.2 C8.2 C9.2 C10.2 C11.1 C12.1 C13.1 C15.2 C16.1 C17.1 C18.2 L1.1 P2.1 R14.2 U1.1 U1.9 U1.24 U1.36 U1.48 U3.5 U4.1 U4.14 | length 1413.7
  Top Layer w8: U4.1 C15.2 C16.1 v1(173.33,1264.69) ; U4.14 C17.1 C18.2 v1(244.69,1264.69) ; v1(295.55,879.45) C12.1 U1.24 ; R14.2 324.35,473.86 309.68,488.53 v1(309.68,490.32) C13.1 309.68,554.68 345.55,590.55 U1.36 ; U1.48 632.95,540.87 C11.1 648.7,474.25 C10.2 ; v1(648.7,391.3) C10.2 ; U1.1 662.21,611.73 662.21,453.51 C10.2 ; U1.9 665.18,769.94 712.11,769.94 733.53,791.36 733.53,821.8 756.42,844.69 C9.2 791.93,860.43 C8.2 823.37,860.43 v1(857.94,895)
  Top Layer w20: v3(865,625.16) 875,615.16 C4.2 U3.5 ; v1(975,926.63) 1001.32,926.63 L1.1
VCC_5V: J2.1 P1.7 P1.8 | length 473.7
  Top Layer w20: P1.8 P1.7 587.71,205 J2.1@719.21,336.5
VCC_CC1101: C5.1 C6.2 C7.2 C22.1 C23.2 C24.1 C25.2 L1.2 U5.4 U5.9 U5.11 U5.14 U5.15 U5.18 | length 1111.7
  Top Layer w8: C6.2 604.13,1175 620.31,1191.18 U5.18 ; v1(585,1345) C7.2 ; U5.15 679.45,1265 659.45,1285 605,1285 C5.1 C7.2 ; U5.14 720.94,1289.06 706.56,1303.44 C7.2 ; U5.4 760.31,1084.69 770,1075 C24.1 ; U5.11 780,1285 798.44,1303.44 853.75,1303.44 C22.1 v1(920,1329.69) ; U5.9 C23.2 885.31,1204.37 v1(924.68,1165)
  Top Layer w10: v1(555,1130) 585,1160 C6.2 ; v1(725,1014.68) 755,1044.68 C24.1
  Top Layer w20: L1.2 v1(1030,1040) 1070,1080 C25.2
pads on no net: U1.2 U1.10 U1.11 U1.20 U1.29 U1.32 U1.33 U1.38 U1.39 U1.41 U1.42 U1.43 U1.45 U1.46 U3.4 U4.2 U4.15 USB1.2 USB1.3 USB1.4 USB1.MH1 USB1.MH2 YA1.2 YA1.4

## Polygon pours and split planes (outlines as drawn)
no net on Multi-Layer (solid): 0,2000
GND on Top Layer "Top Layer-GND" (solid, pour order 0): 0,2000 0,0 1500,0 1500,2000 0,2000
no net on Top Layer "Top Layer-No Net" (solid, pour order 2): 632.95,2360
GND on Bottom Layer "Bottom Layer-GND" (solid, pour order 4): 0,2000 0,0 1500,0 1500,2000 0,2000
GND on GND Plane (split plane): 1454.69,1979.62 1459.27,1978.52 1463.62,1976.72 1467.63,1974.26 1471.21,1971.21 1474.26,1967.63 1476.72,1963.62 1478.52,1959.27 1479.62,1954.69 1479.95,1950.51 1479.9,1950 1479.9,50 1479.95,49.5 1479.62,45.31 1478.52,40.73 1476.72,36.38 1474.26,32.37 1471.21,28.79 1467.63,25.74 1463.62,23.28 1459.27,21.48 1454.69,20.38 1450.5,20.05 1450,20.1 50,20.1 49.5,20.05 45.31,20.38 40.73,21.48 36.38,23.28 32.37,25.74 28.79,28.79 25.74,32.37 23.28,36.38 21.48,40.73 20.38,45.31 20.05,49.5 20.1,50 20.1,1950 20.05,1950.5 20.38,1954.69 21.48,1959.27 23.28,1963.62 25.74,1967.63 28.79,1971.21 32.37,1974.26 36.38,1976.72 40.73,1978.52 45.31,1979.62 49.5,1979.95 50,1979.9 1450,1979.9 1450.51,1979.95
VCC_CC1101 on POWER Plane (split plane): 1454.69,1979.62 1459.27,1978.52 1463.62,1976.72 1467.63,1974.26 1471.21,1971.21 1474.26,1967.63 1476.72,1963.62 1478.52,1959.27 1479.62,1954.69 1479.95,1950.51 1479.9,1950 1479.9,980.1 529.06,980.1 405.1,1104.06 405.1,1300 404.71,1301.95 403.6,1303.6 401.95,1304.71 400,1305.1 20.1,1305.1 20.1,1950 20.05,1950.5 20.38,1954.69 21.48,1959.27 23.28,1963.62 25.74,1967.63 28.79,1971.21 32.37,1974.26 36.38,1976.72 40.73,1978.52 45.31,1979.62 49.5,1979.95 50,1979.9 1450,1979.9 1450.51,1979.95
VCC on POWER Plane (split plane): 1479.9,50 1479.95,49.5 1479.62,45.31 1478.52,40.73 1476.72,36.38 1474.26,32.37 1471.21,28.79 1467.63,25.74 1463.62,23.28 1459.27,21.48 1454.69,20.38 1450.5,20.05 1450,20.1 1030.1,20.1 1030.1,622.79 1103.65,696.35 1104.76,698 1105.15,699.95 1105.15,969.9 1479.9,969.9
VCC_3V on POWER Plane (split plane): 394.9,1101.95 395.29,1100 396.4,1098.35 523.35,971.4 525,970.29 526.95,969.9 1094.95,969.9 1094.95,702.06 1021.4,628.51 1020.29,626.85 1019.9,624.9 1019.9,20.1 50,20.1 49.5,20.05 45.31,20.38 40.73,21.48 36.38,23.28 32.37,25.74 28.79,28.79 25.74,32.37 23.28,36.38 21.48,40.73 20.38,45.31 20.05,49.5 20.1,50 20.1,1294.9 394.9,1294.9

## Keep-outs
Keep-Out Layer:
  the board outline again, w10

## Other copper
POWER Plane (plane layer: these items are gaps in the copper):
  lines w10: 0,1300 400,1300 400,1101.95 526.95,975 1100.05,975 ; 1025,0 1025,624.9 1100.05,699.95 1100.05,975 ; 1500,975 1100.05,975

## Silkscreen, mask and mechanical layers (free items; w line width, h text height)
Top Overlay:
  text "RFID_CC1101 / 433MHz / Rev2.2 / 2021.8.10" at 1095,1915 h40 r270
Bottom Overlay:
  text "SOLAR" at 680,240 h26
  text "BAT" at 900,240 h26

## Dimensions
0,0 to 0,2000 on Top Layer
0,0 to 1500,0 on Top Layer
